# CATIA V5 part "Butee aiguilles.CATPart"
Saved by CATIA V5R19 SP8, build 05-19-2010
Part number: l7-axk1226_1
Nomenclature: 70_h
Source: Unknown
Description: PART-l7-axk1226_1-DESC
Bounding box of the stored display mesh (mm): x 0 to 2, y -13 to 13, z -12.99 to 13
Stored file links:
  C:\Users\rphgr\Desktop\0_Tapis_TC520B_vitesse\Butee aiguilles.CATPart
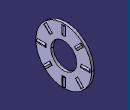
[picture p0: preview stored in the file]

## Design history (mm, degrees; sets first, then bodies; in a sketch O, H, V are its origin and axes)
Body1 "l7-axk1226_1" (main body)
  Solid1: solid without history
  AxisSystem1: origin (0, 0, 0), X (1, 0, 0), Y (0, 1, 0), Z (0, 0, 1)
Body2 "l7-axk1226_2"
  Solid2: solid without history
Body3 "l7-axk1226_3"
  Solid3: solid without history
Body4 "l7-axk1226_4"
  Solid4: solid without history
Body5 "l7-axk1226_5"
  Solid5: solid without history
Body6 "l7-axk1226_6"
  Solid6: solid without history
Body7 "l7-axk1226_7"
  Solid7: solid without history
Body8 "l7-axk1226_8"
  Solid8: solid without history
Body9 "l7-axk1226_9"
  Solid9: solid without history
